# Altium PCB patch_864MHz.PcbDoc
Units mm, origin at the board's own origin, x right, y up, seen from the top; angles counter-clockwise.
Board outline 150 x 150 mm, 2 copper layers (Top Layer, Bottom Layer); 0 components, 2 nets, 1 pads, 0 vias.
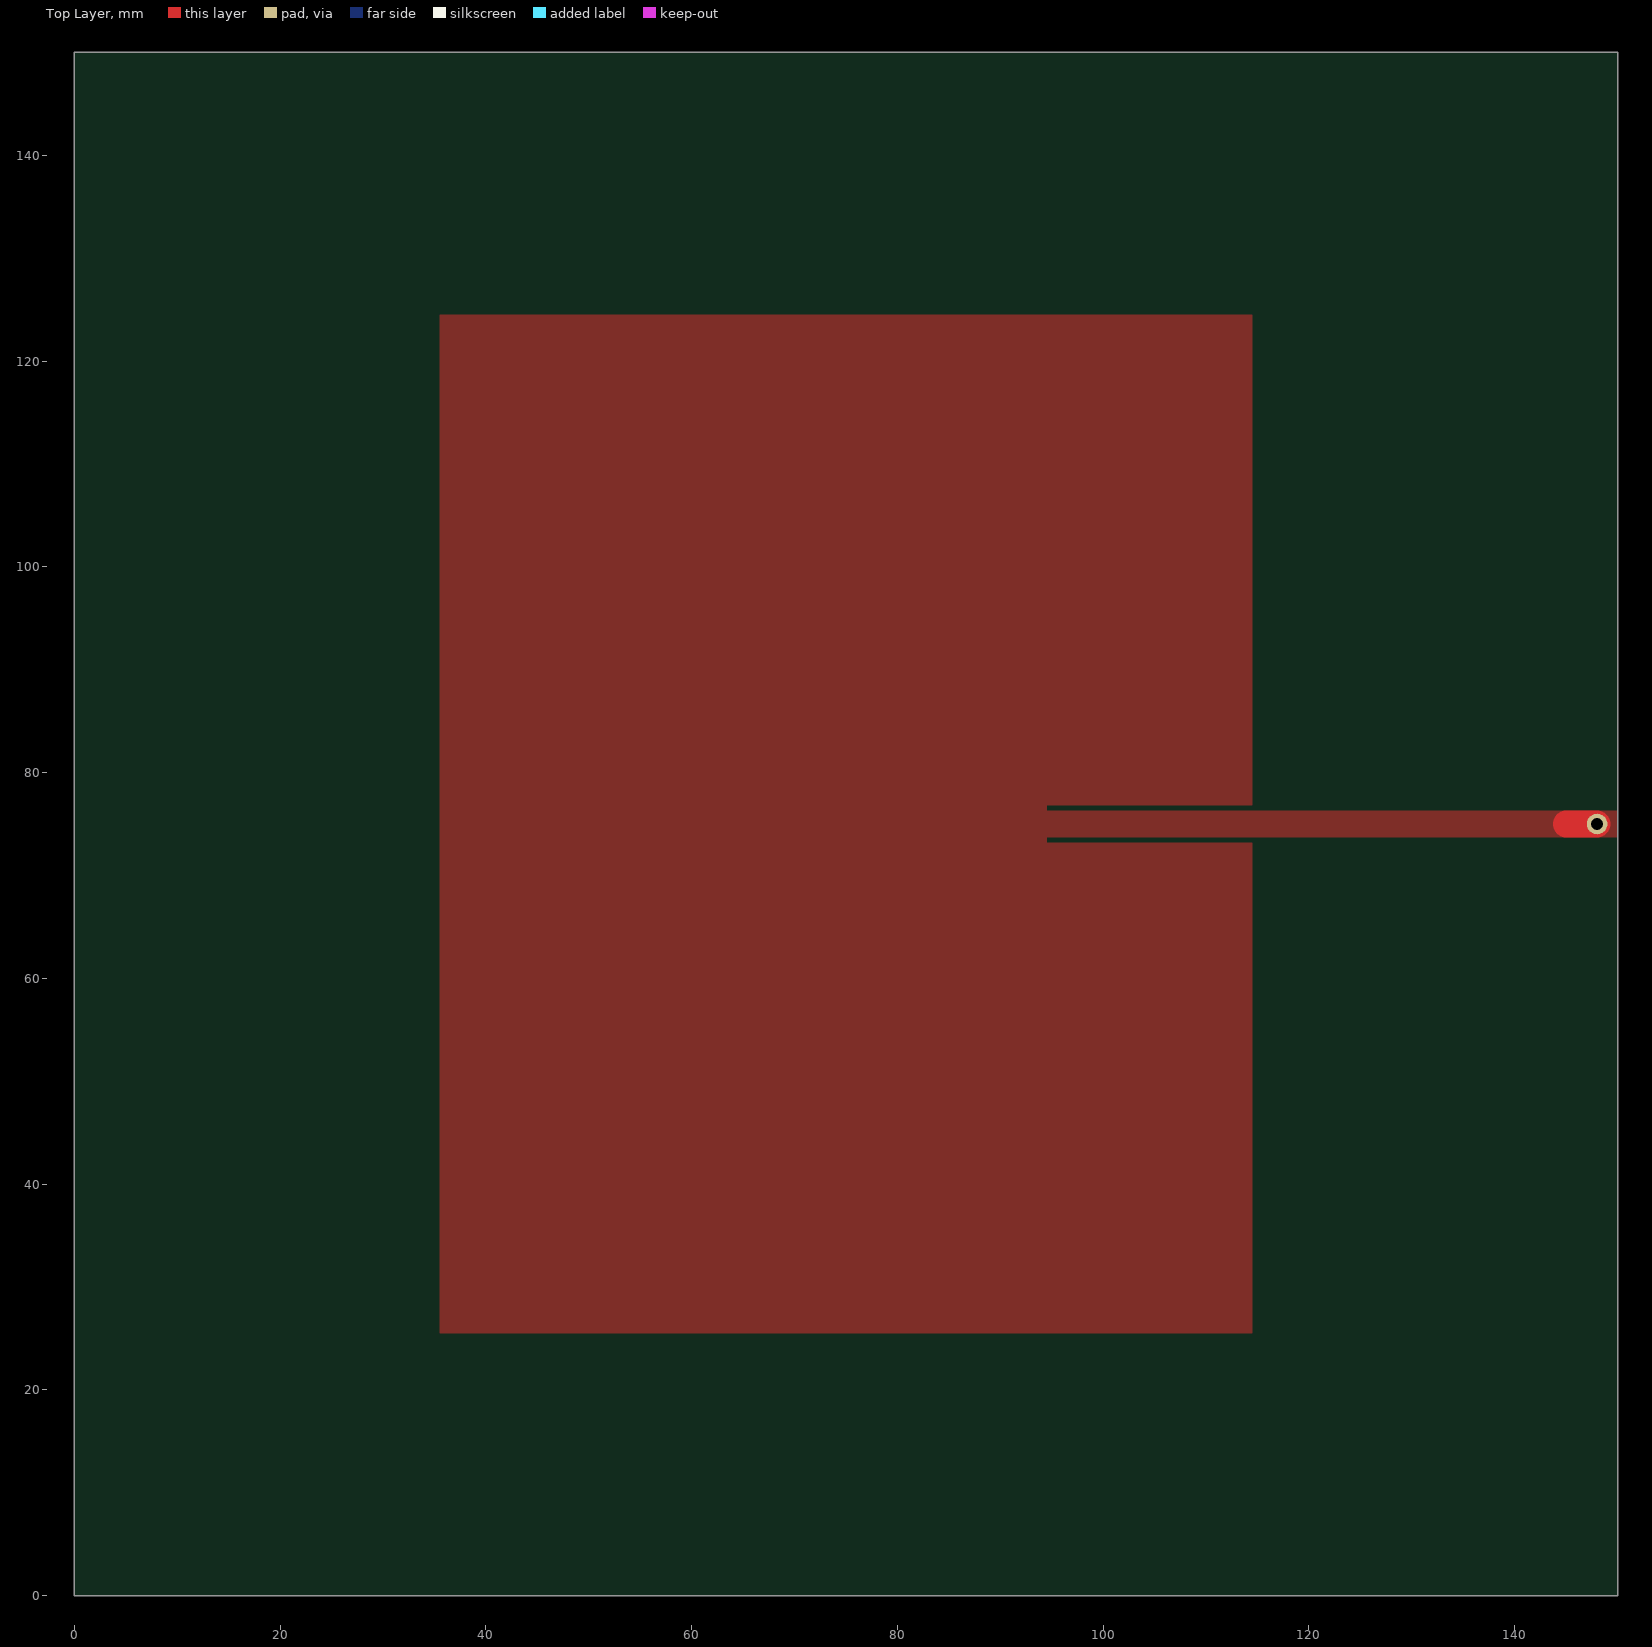
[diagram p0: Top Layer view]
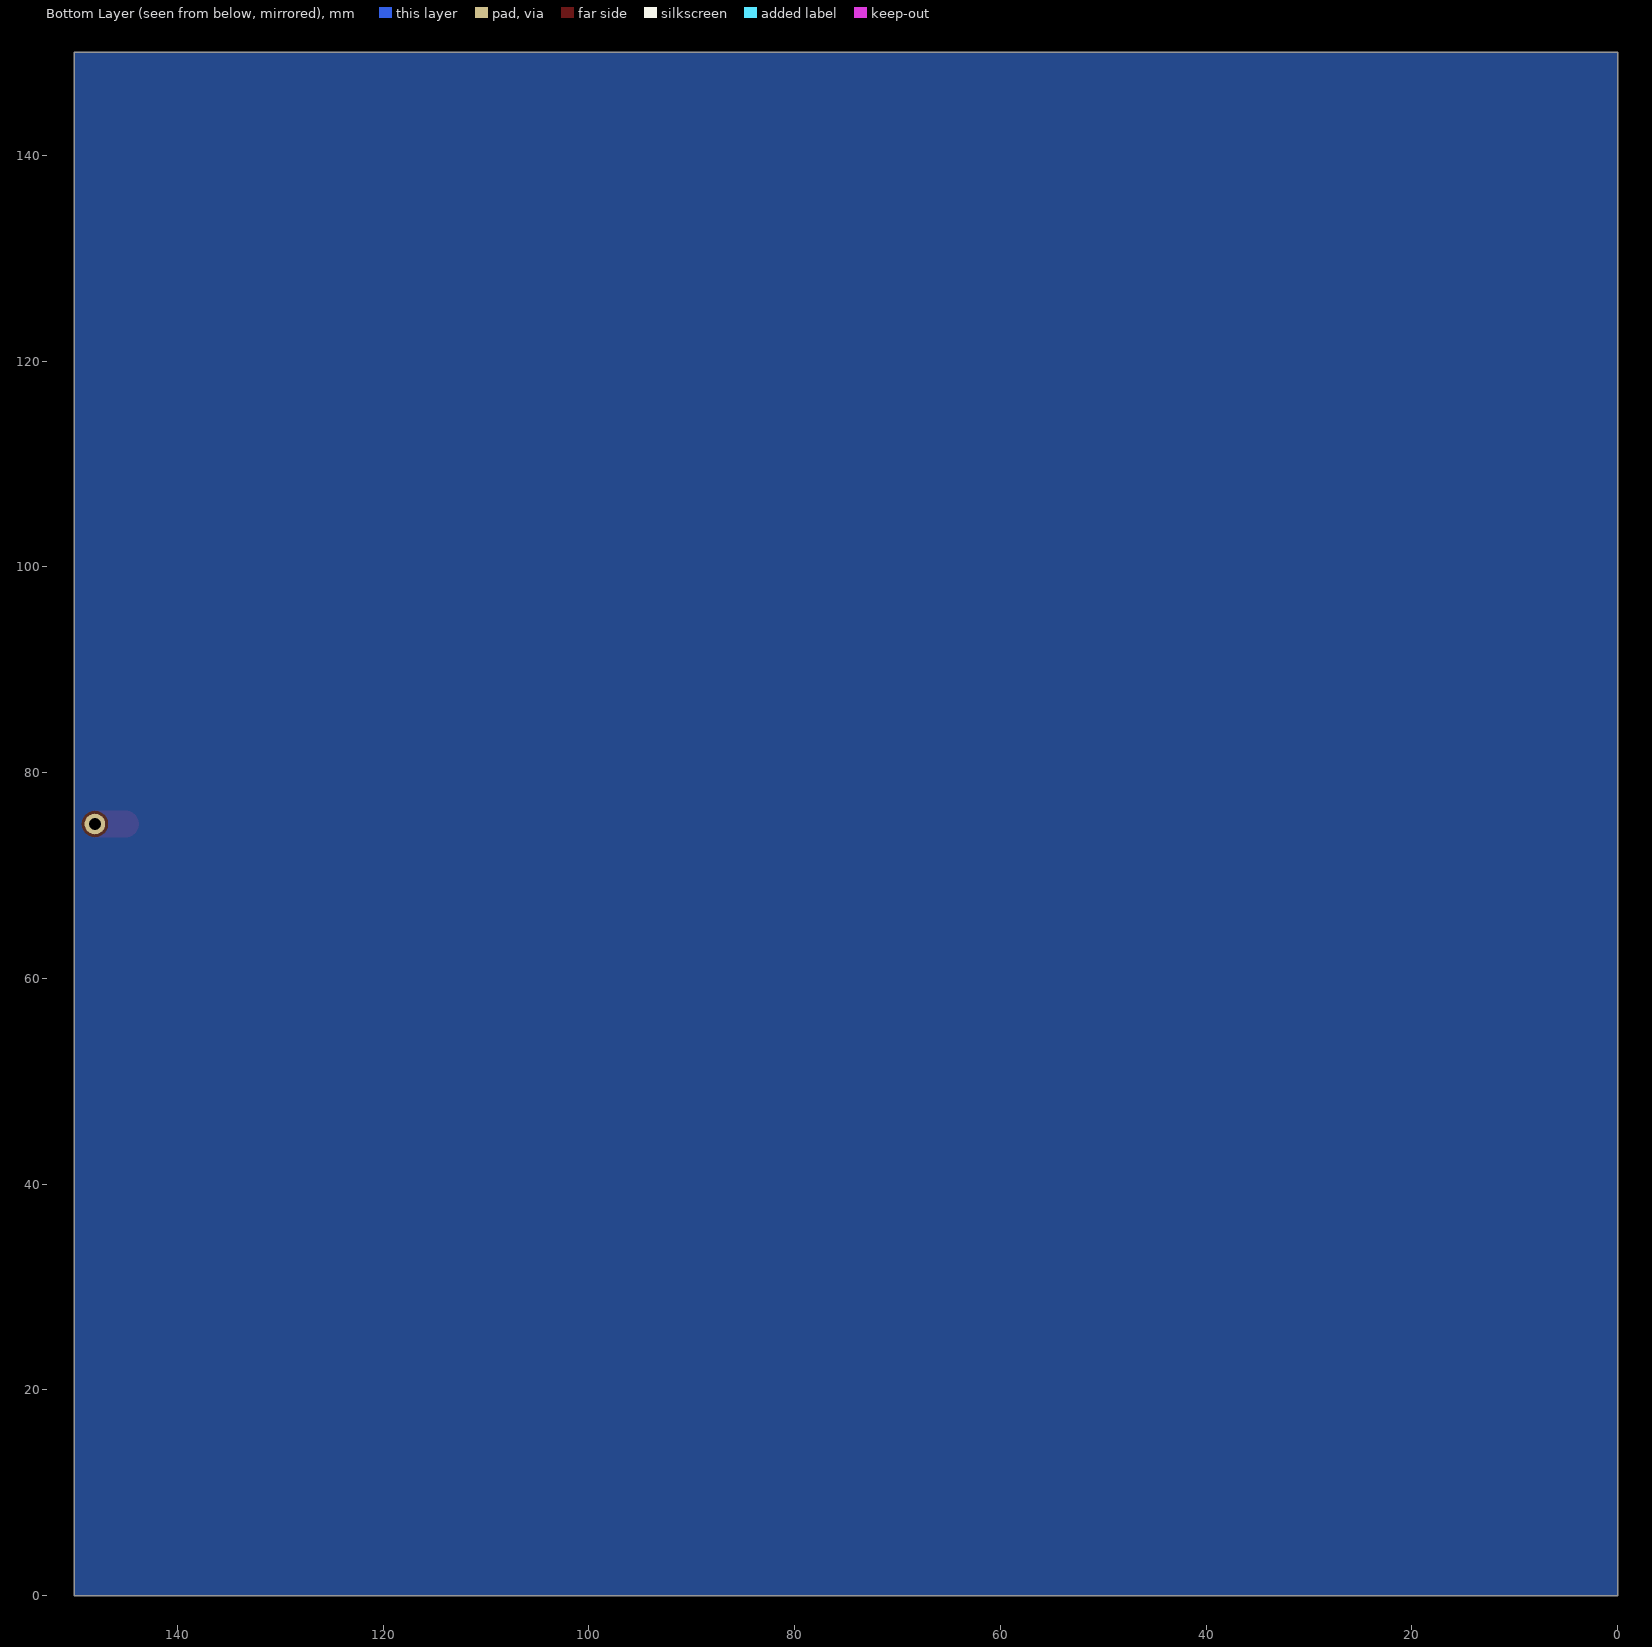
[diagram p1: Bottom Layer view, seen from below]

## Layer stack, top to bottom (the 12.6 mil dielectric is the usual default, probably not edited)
Top Solder: solder mask 0.0102, Solder Resist, Dk 3.5
Top Layer: signal copper 0.0356
Dielectric 1: dielectric 0.32, FR-4, Dk 4.8
Bottom Layer: signal copper 0.0356
Bottom Solder: solder mask 0.0102, Solder Resist, Dk 3.5

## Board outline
0,0 150,0 150,150 0,150

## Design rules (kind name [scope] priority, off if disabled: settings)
Clearance [All] p1: gap=0.254 ignorepadtopadclearanceinfootprint=FALSE except(0: Arc-Hole Track-Hole SMDPad-Hole THPad-Hole Via-Hole Fill-Hole Poly-Hole Region-Hole Text-Hole)
PolygonConnect [All] p1: connectstyle=Relief reliefconductorwidth=0.254 reliefentries=4 polygonreliefangle="90 Angle" airgapwidth=0.254
RoutingVias [All] p1: holewidth=0.711 width=1.27 viastyle="Through Hole" minholewidth=0.711 minwidth=1.27 maxholewidth=0.711 maxwidth=1.27
SolderMaskExpansion [All] p1: expansion=0.102
Width [All] p1: maxlimit=0.254 minlimit=0.254 preferedwidth=0.254
30 further rules are at their usual default settings.

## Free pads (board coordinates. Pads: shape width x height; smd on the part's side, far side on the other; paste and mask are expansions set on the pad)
  round 2 hole 1.2 paste+0 mask+0: 4(148,75)

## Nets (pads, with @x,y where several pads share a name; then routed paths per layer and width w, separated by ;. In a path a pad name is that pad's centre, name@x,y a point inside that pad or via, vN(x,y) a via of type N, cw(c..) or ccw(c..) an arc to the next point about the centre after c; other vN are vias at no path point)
GND: 
Patch: pad.4 | length 3
  Top Layer w2.6: 145,75 pad.4

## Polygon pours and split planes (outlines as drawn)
Patch on Top Layer "Top Layer-No Net" (solid, pour order 4): 35.5,124.5 114.5,124.5 114.5,76.8 94.5,76.8 94.5,76.3 150,76.3 150,73.7 94.5,73.7 94.5,73.2 114.5,73.2 114.5,25.5 35.5,25.5
no net on Bottom Layer "Bottom Layer-No Net" (solid, pour order 8): 155,173
GND on Bottom Layer "Bottom Layer-No Net 1" (solid, pour order 6): 150,150 150,0 0,0 0,150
